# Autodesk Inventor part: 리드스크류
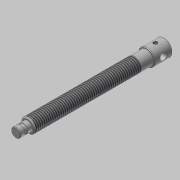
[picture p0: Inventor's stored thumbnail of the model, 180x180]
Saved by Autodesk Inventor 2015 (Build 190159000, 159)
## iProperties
Created: 2019-04
Part Number: 리드스크류
Material: 강철, 연강
Document SubType Name: Modeling
Designer: mduedu
Density: 1 g/cm^3
Appearance: 강철
Author: mduedu
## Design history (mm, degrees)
sketch "스케치1"
  geometry: C1 r 6 at (0, 0); 1 further point
  constraints: 1 centre point, 1 coincident
  dimensions: "d0" = 12 diameter of C1
extrude "돌출1" new body sketch "스케치1" distance "d1" = 100; taper "d2" = 0 deg
sketch "스케치2"
  geometry: C1 r 4 at (0, 0); 1 further point
  constraints: 1 centre point, 1 coincident
  dimensions: "d3" = 8 diameter of C1
extrude "돌출2" join sketch "스케치2" distance "d4" = 10; taper "d5" = 0 deg
sketch "스케치3"
  geometry: C1 r 7 at (0, 0); 1 further point
  constraints: 1 centre point, 1 coincident
  dimensions: "d9" = 14 diameter of C1
extrude "돌출3" join sketch "스케치3" distance "d10" = 15; taper "d11" = 0 deg
feature "스레드1" dims "d12" = 90, "d13" = 0
chamfer "모따기2" distance "d14" = 1; stored, may be unused: second distance "d15" = 2, angle "d16" = 45 deg
chamfer "모따기3" distance "d17" = 0.5; stored, may be unused: second distance "d18" = 2, angle "d19" = 45 deg
chamfer "모따기4" distance "d20" = 0.5; stored, may be unused: second distance "d21" = 2, angle "d22" = 45 deg
sketch "스케치4"
  geometry: L1 (-100, -5)-(-100, 5) reference; L2 (-109.5, 4)-(-109.5, -4) reference; L3 (-109.5, 0)-(-100, 0); C1 r 1.25 at (-105, 4); 1 further point
  constraints: 2 end point, 2 midpoint, 1 centre point
  dimensions: "d23" = 2.5 diameter of C1; "d24" = 5 distance from line of C1.centre L1; "d25" = 4 distance from line of C1.centre L3
revolve "회전1" sketch "스케치4" stored, may be unused: angle "d26" = 90 deg
sketch "스케치5"
  geometry: L1 (0, -6.5)-(0, 6.5) reference; C1 r 3 at (7.5, 0); 2 further points
  constraints: 1 centre point, 1 horizontal alignment, 1 midpoint
  dimensions: "d27" = 6 diameter of C1; "d28" = 7.5 distance from line of C1.centre L1
extrude "돌출4" cut sketch "스케치5" stored distance "d29" = 15; taper "d30" = 0 deg
node "작업 평면1"
sketch "스케치6"
  geometry: L1 (0, 6.5)-(0, -6.5) reference; 2 further points
  constraints: 1 horizontal alignment
  dimensions: "d31" = 7.5 distance from line of point (-7.5, 0) L1
hole "구멍1" sketch "스케치6" at (-7.5, 0) diameter "d32" = 3.242; stored, may be unused: countersink angle "d36" = 90 deg, drill point angle "d38" = 118 deg; dims "d33" = 6, "d34" = 4, "d35" = 2, "d37" = 8
node "솔리드1"
